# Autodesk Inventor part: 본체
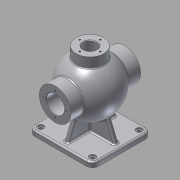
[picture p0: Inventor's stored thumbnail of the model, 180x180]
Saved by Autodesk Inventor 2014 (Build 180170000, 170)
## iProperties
Created: 2015-10
Part Number: 본체
Material: 알루미늄 6061
Document SubType Name: Modeling
Designer: youjin18
Density: 2.71 g/cm^3
Appearance: 알루미늄 - 평지
Mass: 1509.57 g
Surface Area: 1153.7 cm^2
Volume: 557.037 cm^3
Author: youjin18
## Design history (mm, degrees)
sketch "스케치1"
  geometry: L1 (62.5, 57.5)-(-62.5, 57.5); L2 (-62.5, 57.5)-(-62.5, -57.5); L3 (-62.5, -57.5)-(62.5, -57.5); L4 (62.5, -57.5)-(62.5, 57.5); L5 (62.5, 57.5)-(-62.5, -57.5); L6 (-62.5, 57.5)-(62.5, -57.5); 1 further point
  constraints: 12 end point, 2 midpoint, 2 parallel, 1 horizontal, 1 perpendicular
  dimensions: "d0" = 125 distance of L3.end L2.end; "d1" = 115 distance of L2.end L1.end
extrude "돌출1" new body sketch "스케치1" distance "d2" = 10; taper "d3" = 0 deg
fillet "모깎기1" dims "d4" = 12
sketch "스케치2"
  geometry: A1 r 12 centre (50.5, -45.5) between (50.5, -57.5) and (62.5, -45.5) reference; A2 r 12 centre (50.5, 45.5) between (62.5, 45.5) and (50.5, 57.5) reference; A3 r 12 centre (-50.5, 45.5) between (-50.5, 57.5) and (-62.5, 45.5) reference; A4 r 12 centre (-50.5, -45.5) between (-62.5, -45.5) and (-50.5, -57.5) reference; 5 further points
  constraints: 4 coincident
hole "구멍1" sketch "스케치2" at (-50.5, 45.5), (50.5, 45.5), (50.5, -45.5), (-50.5, -45.5) diameter "d5" = 8; stored, may be unused: countersink angle "d9" = 90 deg, drill point angle "d11" = 118 deg; dims "d6" = 6, "d7" = 12, "d8" = 3, "d10" = 8
sketch "스케치3"
  geometry: L1 (-16.741, 34.713)-(16.741, 135.287); C1 r 53 at (0, 85); A1 r 53 centre (0, 85) between (-16.741, 34.713) and (16.741, 135.287); 1 further point
  constraints: 2 centre point, 2 end point, 2 point on circle, 1 coincident, 1 midpoint, 1 vertical alignment
  dimensions: "d12" = 106 diameter of C1; "d13" = 85 distance of point (0, 0) C1.centre; "d14" = 106 diameter of A1
revolve "회전1" sketch "스케치3" stored, may be unused: angle "d15" = 90 deg
sketch "스케치4"
  geometry: C1 r 31 at (0, 85); 1 further point
  constraints: 1 centre point, 1 vertical alignment
  dimensions: "d16" = 62 diameter of C1; "d17" = 85 distance of point (0, 0) C1.centre
extrude "돌출2" join sketch "스케치4" stored distance "d18" = 136; taper "d19" = 0 deg
node "작업 평면1"
sketch "스케치5"
  geometry: C1 r 27 at (0, 0); 1 further point
  constraints: 1 centre point, 1 coincident
  dimensions: "d21" = 54 diameter of C1
extrude "돌출3" join sketch "스케치5" stored distance "d22" = 136; taper "d23" = 0 deg
sketch "스케치7"
  geometry: L1 (45.5, 10)-(-45.5, 10) reference; L2 (-33.719, 44.109)-(-47.5, 10); L3 (33.719, 44.109)-(47.5, 10); L4 (57.5, 10)-(57.5, 0) reference; L5 (-57.5, 0)-(-57.5, 10) reference; A1 r 53 centre (0, 85) between (42.988, 116) and (42.988, 54) reference; 1 further point
  constraints: 4 end point, 2 point on circle, 2 point on line
  dimensions: "d30" = 22 deg angle of L4 L3; "d31" = 22 deg angle of L5 L2; "d32" = 10 distance from line of L5 L2.end; "d33" = 10 horizontal distance of L4.end L3.end
sketch "스케치8"
  geometry: L1 (32.24, 56.547)-(-32.24, 113.453); A1 r 53 centre (0, 85) between (-27, 130.607) and (27, 130.607) reference; A2 r 43 centre (0, 85) between (32.24, 56.547) and (-32.24, 113.453); 1 further point
  constraints: 2 end point, 2 point on circle, 1 centre point, 1 coincident, 1 midpoint
  dimensions: "d46" = 86 diameter of A2
revolve "회전2" sketch "스케치8" stored, may be unused: angle "d47" = 90 deg
sketch "스케치9"
  geometry: C1 r 31 at (0, 0) reference; C2 r 17.5 at (0, 0); 1 further point
  constraints: 1 centre point, 1 coincident
  dimensions: "d48" = 35 diameter of C2
extrude "돌출5" cut sketch "스케치9" stored distance "d49" = 8; taper "d50" = 0 deg
chamfer "모따기1" distance "d51" = 1; stored, may be unused: second distance "d52" = 2, angle "d53" = 45 deg
sketch "스케치10"
  geometry: C1 r 31 at (0, 0) reference; C2 r 18.5 at (0, 0) reference; A1 r 22.5 centre (0, 0) between (0, 22.5) and (-22.5, 0); 3 further points
  constraints: 4 point on circle, 2 horizontal alignment, 2 vertical alignment, 1 centre point, 1 coincident
  dimensions: "d54" = 45 diameter of A1
hole "구멍2" sketch "스케치10" at (0, -22.5), (-22.5, 0), (0, 22.5), (22.5, 0) diameter "d55" = 3.242; stored, may be unused: countersink angle "d59" = 90 deg, drill point angle "d61" = 118 deg; dims "d56" = 12, "d57" = 12, "d58" = 3, "d60" = 15
sketch "스케치11"
  geometry: C1 r 31 at (0, 0) reference; C2 r 18.5 at (0, 0) reference; A1 r 24 centre (0, 0) between (0, 24) and (-24, 0); 3 further points
  constraints: 4 point on circle, 2 vertical alignment, 1 centre point, 1 coincident, 1 horizontal alignment
  dimensions: "d62" = 48 diameter of A1
hole "구멍3" sketch "스케치11" at (0, 24), (-24, 0), (0, -24), (23.561, -4.571) diameter "d63" = 3.242; stored, may be unused: countersink angle "d67" = 90 deg, drill point angle "d69" = 118 deg; dims "d64" = 16, "d65" = 12, "d66" = 3, "d68" = 19
node "작업 평면2"
sketch "스케치12"
  geometry: C1 r 31 at (0, 85) reference; C2 r 18.5 at (0, 85); C3 r 17.5 at (0, 85) reference; 1 further point
  constraints: 1 centre point, 1 coincident
  dimensions: "d71" = 37 diameter of C2
extrude "돌출6" cut sketch "스케치12" distance "d72" = 1.75; taper "d73" = 0 deg
sketch "스케치13"
  geometry: C1 r 27 at (0, 0) reference; C2 r 13 at (0, 0)
  constraints: 1 centre point, 1 coincident
  dimensions: "d74" = 26 diameter of C2
extrude "돌출7" cut sketch "스케치13" stored distance "d75" = 1.75; taper "d76" = 0 deg
chamfer "모따기2" distance "d77" = 1; stored, may be unused: second distance "d78" = 2, angle "d79" = 45 deg
sketch "스케치14"
  geometry: C1 r 27 at (0, 0) reference; C2 r 14 at (0, 0) reference; A1 r 20 centre (0, 0) between (0, 20) and (-20, 0); 2 further points
  constraints: 4 point on circle, 2 horizontal alignment, 2 vertical alignment, 1 centre point, 1 coincident
  dimensions: "d80" = 40 diameter of A1
hole "구멍4" sketch "스케치14" at (0, 20), (-20, 0), (0, -20), (20, 0) diameter "d81" = 3.242; stored, may be unused: countersink angle "d85" = 90 deg, drill point angle "d87" = 118 deg; dims "d82" = 9, "d83" = 12, "d84" = 3, "d86" = 11
fillet "모깎기2" dims "d88" = 3
sketch "스케치16"
  geometry: L1 (4, 4)-(-4, 4); L2 (-4, 4)-(-4, -4); L3 (-4, -4)-(4, -4); L4 (4, -4)-(4, 4); L5 (4, 4)-(-4, -4); L6 (-4, 4)-(4, -4); 1 further point
  constraints: 12 end point, 2 midpoint, 2 parallel, 1 horizontal, 1 perpendicular
  dimensions: "d94" = 8 distance of L3.end L2.end; "d95" = 8 distance of L2.end L1.end
extrude "돌출9" join sketch "스케치16" stored distance "d96" = 1.75; taper "d97" = 0 deg
feature "리브3" dims "d98" = 1, "d99" = 8, "d100" = 0, "d101" = 0, "d102" = 1, "d103" = 1
feature "리브4" dims "d104" = 1, "d105" = 8, "d106" = 0, "d107" = 0, "d108" = 1, "d109" = 1
sketch "스케치17"
  geometry: L1 (50.5, 10)-(-50.5, 10) reference; L2 (-37.379, 47.426)-(-52.5, 10); L3 (37.379, 47.426)-(52.5, 10); L4 (62.5, 10)-(62.5, 0) reference; L5 (-62.5, 0)-(-62.5, 10) reference; A1 r 53 centre (0, 85) between (-28.393, 129.753) and (28.393, 129.753) reference; 1 further point
  constraints: 4 end point, 2 point on circle, 2 point on line
  dimensions: "d110" = 22 deg angle of L4 L3; "d111" = 22 deg angle of L5 L2; "d112" = 10 distance from line of L5 L2.end; "d113" = 10 distance from line of L4 L3.end
feature "리브5" dims "d114" = 1, "d115" = 8, "d116" = 0, "d117" = 0, "d118" = 1, "d119" = 1
feature "리브6" dims "d120" = 1, "d121" = 8, "d122" = 0, "d123" = 0, "d124" = 1, "d125" = 1
fillet "모깎기4" dims "d126" = 3
fillet "모깎기5" dims "d127" = 3
node "작업 평면3"
sketch "스케치18"
  geometry: L1 (-27, 0)-(-27, -17.714) reference; L2 (-27, 0)-(27, 0) reference; 2 further points
  constraints: 1 vertical alignment, 1 other
  dimensions: "d128" = 27 distance from line of point (0, -10) L1 (derived); "d129" = 10 distance from line of L2 point (0, -10)
feature "엠보싱1" sketch "스케치18" dims "d0" = 125, "d1" = 115, "d130" = 0.5, "d131" = 0
node "솔리드1"
other parameters: "d70" = 52
